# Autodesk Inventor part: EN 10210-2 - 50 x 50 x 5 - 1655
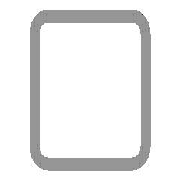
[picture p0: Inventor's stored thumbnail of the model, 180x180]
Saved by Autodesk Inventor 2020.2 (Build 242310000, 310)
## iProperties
Created: 2019-01
Part Number: EN 10210-2 - 50 x 50 x 5 - 1655
Material: Stahl, weich
Description: Rohrleitung
Document SubType Name: Modeling
Standard: DIN
Designer: lutzd
Standard Revision: 2006-07
Standards Organization: DIN
Language: de-DE
Size Designation: 50 x 50 x 5
Categories: <MemberInstance><Categories><Category DisplayName="Profile" InternalName="089c4875-fa83-4c05-b084-43b9cc11f5ed" Mnemonic="GRDR"><CategoryParameter DisplayName="
Stock Number: 50 x 50 x 5
Mass: 11344.1 g
Surface Area: 5620.3 cm^2
Volume: 1445.1 cm^3
Density: 7.85 g/cm^3
Appearance: Semi-Polished(8)
_CCFamilyMember: 16
_CCFamilyDisplayName: DIN EN 10210-2 (USAS B17.1 quadratisch) - Rohrleitung — In Klammern angegebene Größen wurden aufgehoben
_FrameMemberDoc: Frame Member File
_Version: 15.0.0
_GetPNFromCC: 1
G_L: 1655,000 mm
G_W: 50,000 mm
G_H: 50,000 mm
DocNumber: ADSK-014273
Folder: .
Dimensions: 50x50x1655 mm
Mass: 11,344 kg
+698143BA-6676-406A-B1DD-22369AE07F53+SCHNITTDETAIL1: Schnittwinkel 90,00 grd
VLT_Material: Stahl, weich
IsCustomPart: 1
Title: Profil-Bauteil
Author: lutzd
Revision Number: -
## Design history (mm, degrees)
node "Startebene"
node "Endebene"
sketch "Skizze"
  geometry: L1 (-25, -17.5)-(-25, 17.5); L2 (-17.5, 25)-(17.5, 25); L3 (25, 17.5)-(25, -17.5); L4 (17.5, -25)-(-17.5, -25); L5 (-15, 20)-(15, 20); L6 (20, 15)-(20, -15); L7 (15, -20)-(-15, -20); L8 (-20, -15)-(-20, 15); L9 (0, 37.175)-(0, -37.175) reference; L10 (-37.175, 0)-(37.175, 0) reference; A1 r 7.5 centre (-17.5, -17.5) between (-25, -17.5) and (-17.5, -25); A2 r 7.5 centre (-17.5, 17.5) between (-17.5, 25) and (-25, 17.5); A3 r 7.5 centre (17.5, 17.5) between (25, 17.5) and (17.5, 25); A4 r 7.5 centre (17.5, -17.5) between (17.5, -25) and (25, -17.5); A5 r 5 centre (-15, -15) between (-20, -15) and (-15, -20); A6 r 5 centre (-15, 15) between (-15, 20) and (-20, 15); A7 r 5 centre (15, 15) between (20, 15) and (15, 20); A8 r 5 centre (15, -15) between (15, -20) and (20, -15)
  constraints: 16 end point, 16 point on circle, 16 tangent, 8 centre point, 6 equal radius, 4 parallel, 2 perpendicular, 2 other
  dimensions: "d7" = 7.5 radius of A1 (= G_IR); "d10" = 50 distance between parallel lines of L2 L4 (= G_H); "d11" = 50 distance between parallel lines of L1 L3 (= G_W); "d12" = 5 distance between parallel lines of L3 L6 (= G_T); "d15" = 25 distance between parallel lines of L2 L10 (= 0.5 x d10); "d16" = 25 distance between parallel lines of L9 L3 (= 0.5 x d11); "d19" = 5 radius of A5 (= G_T); "d20" = 5 distance between parallel lines of L4 L7 (= G_T)
extrude "Körper" new body sketch "Skizze" stored distance "d3" = 1655 (= G_L); taper "d4" = 0 deg
node "Driven Length"
  sketch "Sketch3"
    geometry: L1 (0, 0)-(10, 0) reference
    constraints: 2 end point, 1 horizontal
  workplane "Work Plane3"
  sketch "Sketch4"
    geometry: L1 (-2, 0)-(12, 0) reference; L2 (-2, 1655)-(12, 1655) reference
    dimensions: "d18" = 1655 distance between parallel lines of L1 L2 (derived)
workplane "Arbeitsebene4"
feature "Trennen1"
body "Solid1"
other parameters: "G_W" = 50 [user parameter; used in 1 equation term], "G_H" = 50 [user parameter; used in 1 equation term], "G_T" = 5 [user parameter; used in 3 equation terms], "G_IR" = 7.5 [user parameter; used in 1 equation term], "G_L" = 1655 (= d18) [user parameter; used in 1 equation term], "G_OFFSET_START" = 0 [user parameter; used in 1 equation term], "d13" = 0 (computed from G_OFFSET_START), "d14" = 1655 (= G_OFFSET_END + B_L), "B_L" = 1705 [user parameter; used in 1 equation term], "d17" = 90 deg
